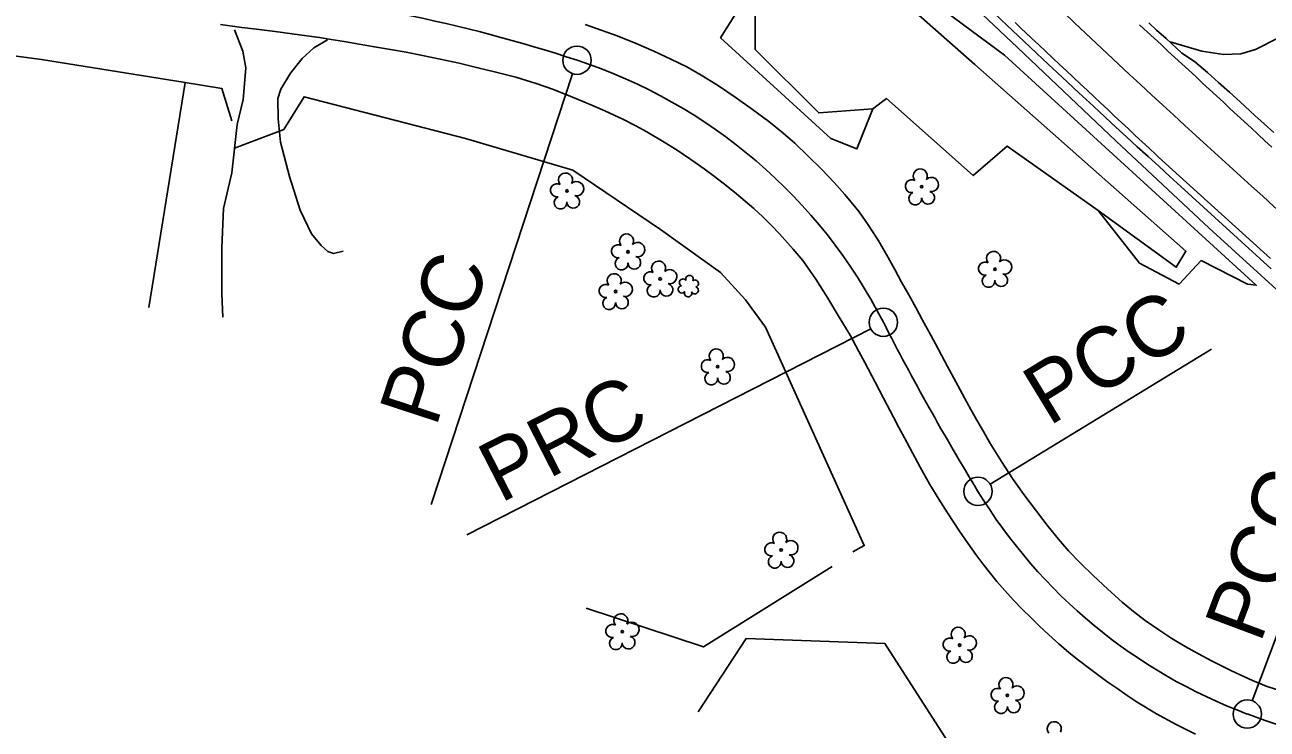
# Model space of a CAD drawing. Extents: x 474972 to 479313, y 498315 to 502691.
# Drawn here: x 476395.3 to 476724.1, y 500512.6 to 500699.1 of the extents above; entities that cross this region are included whole.
import ezdxf

# ---------------------------------------------------------------- set-up
doc = ezdxf.new("R2010")
doc.units = 0
for name, color, linetype in [('Exist Guardrail', 7, 'Continuous'), ('Exist Horizontal Alignment', 7, 'Continuous'), ('Exist Other Culture Fence Line', 7, 'Continuous'), ('Exist Other Culture Gate', 7, 'Continuous'), ('Exist Roads EOP', 7, 'Continuous'), ('Exist Roads EOT', 7, 'Continuous'), ('Exist Roads Soil', 7, 'Continuous'), ('Exist Vegetation Hedge Row', 7, 'Continuous'), ('Exist Vegetation Shrub CELL', 7, 'Continuous'), ('Exist Vegetation Tree CELL', 7, 'Continuous'), ('Exist Vegetation Woods Line', 7, 'Continuous')]:
    doc.layers.add(name, color=color, linetype=linetype)

msp = doc.modelspace()

# ---------------------------------------------------------------- linework, layer by layer
at = {"layer": 'Exist Guardrail'}
msp.add_lwpolyline([(476737.29, 500619.31), (476708.8, 500645.27), (476684.15, 500668.31), (476658.03, 500693.08), (476634.78, 500715.19), (476612.16, 500736.97), (476592.64, 500756.19), (476581.97, 500766.87)], dxfattribs=at)
at = {"layer": 'Exist Horizontal Alignment'}
for p, q in [((476540.3, 500686.15), (476502.88, 500572.1)), ((476619.19, 500618.65), (476512.3, 500564.04)), ((476650.77, 500577.53), (476709.4, 500613.27)), ((476720.16, 500520.15), (476742.19, 500578.94))]:
    msp.add_line(p, q, dxfattribs=at)
for centre in [(476541.46, 500689.72), (476622.53, 500620.35), (476647.57, 500575.58), (476718.85, 500516.64)]:
    msp.add_circle(centre, 3.75, dxfattribs=at)
for centre, radius, start, end in [((478884.49, 503049.53), 3226.8, 223.91157, 228.4381), ((476415.01, 500304.21), 405.72, 71.839, 85.4005), ((476497.81, 500556.65), 140.05, 27.0574, 71.839), ((477230, 500930.64), 682.12, 207.0574, 211.36729), ((476768.56, 500649.33), 141.7, 211.3673, 249.4634), ((476791.99, 500711.88), 208.48, 249.4634, 293.0343)]:
    msp.add_arc(centre, radius, start, end, dxfattribs=at)
at = {"layer": 'Exist Other Culture Fence Line'}
for points in [[(476437.8, 500683.85), (476399.76, 500689.93), (476351.74, 500696.3), (476294.41, 500702.48), (476246.36, 500709.31), (476234.18, 500710.79)], [(476428.15, 500624.27), (476437.8, 500683.85), (476447.45, 500682.25), (476450.13, 500673.64)], [(476463.87, 500671.4), (476469.23, 500680.07), (476511.97, 500668.99), (476540.37, 500660.6), (476563.59, 500644.88), (476579.46, 500633.51), (476586.06, 500626.29), (476591.34, 500619.04), (476617.5, 500561.23), (476614.47, 500559.55)], [(476609, 500555.67), (476574.9, 500534.42), (476543.85, 500544.63)]]:
    msp.add_lwpolyline(points, dxfattribs=at)
at = {"layer": 'Exist Other Culture Gate'}
msp.add_line((476463.87, 500671.4), (476450.85, 500666.47), dxfattribs=at)
at = {"layer": 'Exist Roads EOP'}
for points in [[(476725.18, 500634.51), (476722.2, 500637.21), (476719.22, 500639.91), (476716.24, 500642.63), (476713.25, 500645.35), (476710.25, 500648.08), (476707.26, 500650.82), (476704.25, 500653.56), (476701.27, 500656.29), (476698.33, 500658.98), (476695.43, 500661.63), (476692.58, 500664.24), (476689.74, 500666.83), (476686.91, 500669.43), (476684.09, 500672.03), (476681.26, 500674.64), (476678.12, 500677.55), (476674.31, 500681.08), (476669.86, 500685.23), (476664.75, 500689.98), (476659.67, 500694.76), (476655.28, 500698.9), (476651.57, 500702.41)], [(476705.15, 500511.33), (476700.03, 500513.84), (476694.83, 500516.65), (476689.74, 500519.77), (476687.03, 500521.58), (476684.3, 500523.44), (476681.71, 500525.27), (476679.19, 500527.09), (476676.72, 500528.94), (476674.22, 500530.88), (476671.64, 500532.97), (476668.99, 500535.21), (476666.3, 500537.63), (476663.75, 500540.02), (476661.53, 500542.17), (476659.37, 500544.34), (476657.01, 500546.8), (476654.68, 500549.33), (476652.59, 500551.75), (476648.86, 500556.39), (476646.98, 500558.9), (476644.89, 500561.84), (476642.7, 500565.02), (476639.47, 500569.91), (476637.23, 500573.49), (476634.88, 500577.44), (476632.31, 500581.99), (476629.52, 500587.11), (476628.1, 500589.76), (476626.66, 500592.46), (476625.22, 500595.2), (476622.55, 500600.27), (476620.35, 500604.46), (476617.63, 500609.66), (476616.08, 500612.64), (476613.72, 500616.9), (476610.85, 500621.66), (476607.81, 500626.73), (476604.67, 500631.76), (476601.22, 500636.67), (476598.68, 500639.66), (476595.02, 500643.75), (476592.88, 500646.05), (476590.61, 500648.3), (476588.26, 500650.46), (476583.68, 500654.35), (476580.95, 500656.52), (476577.82, 500658.95), (476575.1, 500660.99), (476572.77, 500662.67), (476568.21, 500665.73), (476564.99, 500667.8), (476559.92, 500670.79), (476556.83, 500672.42), (476553.73, 500673.99), (476548.84, 500676.33), (476546.16, 500677.5), (476543.27, 500678.71), (476540.27, 500679.96), (476535.26, 500681.95), (476530.64, 500683.59), (476525.26, 500685.23), (476519.98, 500686.58), (476515.25, 500687.73), (476510.26, 500688.9), (476505.21, 500690.04), (476500.54, 500691.01), (476496.28, 500691.81), (476492.07, 500692.56), (476487.87, 500693.29), (476483.78, 500694), (476479.87, 500694.66), (476476.39, 500695.23), (476473.29, 500695.72), (476469.92, 500696.21), (476466.12, 500696.73), (476461.62, 500697.31), (476456.63, 500697.92), (476452.79, 500698.42), (476447.08, 500699.21)], [(476543.63, 500699.17), (476546.59, 500698.15), (476552.05, 500696.15), (476557.11, 500694.15), (476561.75, 500692.11), (476566.27, 500690.03), (476570.5, 500687.93), (476574.34, 500685.8), (476578.68, 500683.09), (476583.34, 500679.92), (476587.93, 500676.67), (476592.25, 500673.48), (476595.95, 500670.53), (476599.13, 500667.76), (476602.5, 500664.52), (476606.23, 500660.82), (476609.5, 500657.38), (476612.37, 500654.16), (476616.16, 500649.55), (476618.56, 500646.17), (476621.18, 500642.08), (476623.79, 500637.48), (476625.54, 500634.29), (476627.38, 500630.97), (476629.26, 500627.62), (476631.1, 500624.27), (476632.91, 500620.94), (476634.65, 500617.72), (476636.33, 500614.64), (476637.94, 500611.65), (476639.51, 500608.68), (476642.23, 500603.61), (476644.08, 500600.19), (476645.69, 500597.26), (476647.27, 500594.46), (476649.01, 500591.41), (476650.74, 500588.43), (476653.76, 500583.47), (476656.72, 500578.98), (476659.75, 500574.75), (476663.06, 500570.35), (476666.18, 500566.3), (476668.86, 500562.91), (476671.5, 500559.86), (476674.65, 500556.62), (476678.07, 500553.29), (476681.94, 500549.73), (476685.77, 500546.27), (476688.72, 500543.77), (476691.83, 500541.43), (476695.42, 500538.93), (476698.9, 500536.65), (476702.44, 500534.53), (476705.91, 500532.55), (476709.41, 500530.72), (476714.47, 500528.15), (476718.3, 500526.36), (476720.25, 500525.49), (476723.88, 500524.03), (476729.31, 500522.29)], [(476692.78, 500699.62), (476694.85, 500697.72), (476697.34, 500695.44), (476701.54, 500691.63), (476704.85, 500689.41), (476708.28, 500686.48), (476711.23, 500683.85), (476714.11, 500681.25), (476716.93, 500678.69), (476720.85, 500675.13), (476723.29, 500672.9), (476725.87, 500670.56)]]:
    msp.add_lwpolyline(points, dxfattribs=at)
at = {"layer": 'Exist Roads EOT'}
for points in [[(476724.98, 500637.21), (476723.12, 500638.89), (476721.27, 500640.57), (476719.42, 500642.25), (476717.57, 500643.93), (476715.72, 500645.61), (476713.87, 500647.29), (476712.02, 500648.97), (476710.17, 500650.65), (476708.32, 500652.33), (476706.47, 500654.01), (476704.62, 500655.69), (476702.77, 500657.37), (476700.92, 500659.05), (476699.07, 500660.73), (476697.22, 500662.41), (476695.37, 500664.09), (476694.7, 500664.7), (476692.87, 500666.41), (476691.05, 500668.12), (476689.22, 500669.83), (476687.4, 500671.54), (476685.57, 500673.24), (476683.75, 500674.95), (476681.93, 500676.66), (476680.1, 500678.37), (476678.28, 500680.08), (476676.45, 500681.79), (476674.63, 500683.5), (476672.8, 500685.21), (476670.98, 500686.92), (476669.16, 500688.63), (476667.33, 500690.34), (476665.51, 500692.05), (476663.68, 500693.76), (476661.86, 500695.47), (476660.03, 500697.17), (476659.19, 500697.96), (476657.38, 500699.69)], [(476725.37, 500666.7), (476723.53, 500668.39), (476721.7, 500670.09), (476719.87, 500671.79), (476718.03, 500673.49), (476716.2, 500675.18), (476714.36, 500676.88), (476712.53, 500678.58), (476710.69, 500680.28), (476708.86, 500681.98), (476707.02, 500683.67), (476705.19, 500685.37), (476703.36, 500687.07), (476701.52, 500688.77), (476699.69, 500690.46), (476697.85, 500692.16), (476696.02, 500693.86), (476694.18, 500695.56), (476692.35, 500697.26), (476690.52, 500698.95), (476690.32, 500699.13)]]:
    msp.add_lwpolyline(points, dxfattribs=at)
at = {"layer": 'Exist Roads Soil'}
msp.add_line((476453.04, 500692.11), (476450.83, 500697.77), dxfattribs=at)
for points in [[(476698.43, 500694.57), (476706.83, 500692.14), (476712.54, 500691.21), (476717.15, 500691.43), (476721, 500692.58), (476727.29, 500695.72), (476733.62, 500700.65), (476743.74, 500710.34), (476757.73, 500725.73), (476770.36, 500737.78), (476783.01, 500748.93), (476797.48, 500762.55), (476812.27, 500777.94), (476819.37, 500785.2)], [(476475.39, 500695.14), (476471.79, 500692.99), (476468.73, 500690.18), (476465.66, 500686.32), (476463.1, 500682.07), (476462.29, 500679.56), (476462.38, 500674.16), (476462.98, 500668.02), (476465.33, 500658.95), (476468.23, 500650), (476471.2, 500643.75), (476473.75, 500640.66), (476475.54, 500639.08), (476477.06, 500638.52), (476479.6, 500639.18)], [(476447.74, 500621.69), (476447.45, 500627.87), (476447.5, 500640.05), (476447.93, 500650.44), (476450.14, 500659.93), (476451.52, 500672.7), (476453.09, 500679.29), (476453.86, 500687.71), (476453.04, 500692.11)]]:
    msp.add_lwpolyline(points, dxfattribs=at)
at = {"layer": 'Exist Vegetation Hedge Row'}
for points in [[(476586.98, 500753.69), (476594.5, 500750.7), (476628.01, 500716.75), (476632.55, 500707.49), (476654.57, 500691.08), (476721.24, 500630.13), (476718.92, 500630.47), (476706.65, 500636.66), (476700.86, 500630.44), (476690.28, 500636), (476679.38, 500649.98)], [(476619.72, 500676.82), (476615.54, 500666.22), (476608.61, 500669.04), (476579.48, 500695.65), (476587.09, 500707.88), (476600.68, 500710.32)]]:
    msp.add_lwpolyline(points, dxfattribs=at)
at = {"layer": 'Exist Vegetation Shrub CELL'}
msp.add_line((476571, 500629.74), (476571, 500629.74), dxfattribs=at)
for centre, radius, start, end in [((476571.23, 500631.78), 0.99, 334.8391, 200.4717), ((476569.2, 500629.04), 0.955, 95.1099, 327.9534), ((476569.52, 500630.87), 0.968, 35.8908, 245.4216), ((476572.64, 500628.81), 0.937, 204.9913, 73.4601), ((476572.68, 500630.61), 0.929, 284.4567, 126.0861), ((476570.87, 500628.06), 0.984, 151.2797, 21.387)]:
    msp.add_arc(centre, radius, start, end, dxfattribs=at)
at = {"layer": 'Exist Vegetation Tree CELL'}
for p, q in [((476538.79, 500655.13), (476538.79, 500655.13)), ((476632.69, 500656.22), (476632.69, 500656.22)), ((476554.94, 500639), (476554.94, 500639)), ((476652.06, 500634.39), (476652.06, 500634.39)), ((476563.46, 500631.83), (476563.46, 500631.83)), ((476551.67, 500628.49), (476551.67, 500628.49)), ((476578.69, 500608.58), (476578.69, 500608.58)), ((476595.5, 500560.06), (476595.5, 500560.06)), ((476553.44, 500538.46), (476553.44, 500538.46)), ((476642.72, 500534.87), (476642.72, 500534.87)), ((476655.37, 500521.58), (476655.37, 500521.58))]:
    msp.add_line(p, q, dxfattribs=at)
for centre in [(476538.79, 500655.13), (476632.69, 500656.22), (476554.94, 500639), (476563.46, 500631.83), (476652.06, 500634.39), (476551.67, 500628.49), (476578.69, 500608.58), (476595.5, 500560.06), (476553.44, 500538.46), (476642.72, 500534.87), (476655.37, 500521.58)]:
    msp.add_circle(centre, 0.326, dxfattribs=at)
for centre, radius, start, end in [((476538.41, 500658.01), 1.86, 330.1651, 219.7134), ((476632.31, 500659.09), 1.86, 330.1651, 219.7134), ((476635.24, 500656.81), 1.9, 257.1011, 134.1999), ((476536.19, 500655.29), 1.73, 62.6636, 279.3457), ((476541.34, 500655.72), 1.9, 257.1011, 134.1999), ((476630.09, 500656.37), 1.73, 62.6636, 279.3457), ((476537.09, 500652.01), 1.69, 111.5671, 6.231), ((476540.46, 500652.23), 1.7, 181.2822, 74.56), ((476630.99, 500653.1), 1.69, 111.5671, 6.231), ((476634.37, 500653.32), 1.7, 181.2822, 74.56), ((476554.56, 500641.87), 1.86, 330.1651, 219.7134), ((476552.34, 500639.15), 1.73, 62.6636, 279.3457), ((476557.49, 500639.59), 1.9, 257.1011, 134.1999), ((476651.68, 500637.27), 1.86, 330.1651, 219.7134), ((476553.24, 500635.88), 1.69, 111.5671, 6.231), ((476556.62, 500636.1), 1.7, 181.2822, 74.56), ((476563.07, 500634.7), 1.86, 330.1651, 219.7134), ((476649.46, 500634.55), 1.73, 62.6636, 279.3457), ((476654.61, 500634.98), 1.9, 257.1011, 134.1999), ((476551.29, 500631.36), 1.86, 330.1651, 219.7134), ((476560.85, 500631.98), 1.73, 62.6636, 279.3457), ((476566.01, 500632.42), 1.9, 257.1011, 134.1999), ((476650.36, 500631.27), 1.69, 111.5671, 6.231), ((476653.73, 500631.49), 1.7, 181.2822, 74.56), ((476549.07, 500628.64), 1.73, 62.6636, 279.3457), ((476554.22, 500629.08), 1.9, 257.1011, 134.1999), ((476561.75, 500628.71), 1.69, 111.5671, 6.231), ((476565.13, 500628.93), 1.7, 181.2822, 74.56), ((476549.97, 500625.37), 1.69, 111.5671, 6.231), ((476553.35, 500625.59), 1.7, 181.2822, 74.56), ((476578.31, 500611.45), 1.86, 330.1651, 219.7134), ((476576.08, 500608.73), 1.73, 62.6636, 279.3457), ((476581.24, 500609.17), 1.9, 257.1011, 134.1999), ((476576.99, 500605.46), 1.69, 111.5671, 6.231), ((476580.36, 500605.68), 1.7, 181.2822, 74.56), ((476595.11, 500562.93), 1.86, 330.1651, 219.7134), ((476592.89, 500560.21), 1.73, 62.6636, 279.3457), ((476598.05, 500560.65), 1.9, 257.1011, 134.1999), ((476593.79, 500556.94), 1.69, 111.5671, 6.231), ((476597.17, 500557.16), 1.7, 181.2822, 74.56), ((476550.83, 500538.61), 1.73, 62.6636, 279.3457), ((476553.05, 500541.33), 1.86, 330.1651, 219.7134), ((476555.99, 500539.05), 1.9, 257.1011, 134.1999), ((476551.73, 500535.34), 1.69, 111.5671, 6.231), ((476555.11, 500535.56), 1.7, 181.2822, 74.56), ((476642.34, 500537.74), 1.86, 330.1651, 219.7134), ((476645.27, 500535.46), 1.9, 257.1011, 134.1999), ((476640.11, 500535.02), 1.73, 62.6636, 279.3457), ((476644.39, 500531.97), 1.7, 181.2822, 74.56), ((476641.02, 500531.75), 1.69, 111.5671, 6.231), ((476654.99, 500524.45), 1.86, 330.1651, 219.7134), ((476657.92, 500522.17), 1.9, 257.1011, 134.1999), ((476652.77, 500521.73), 1.73, 62.6636, 279.3457), ((476653.67, 500518.46), 1.69, 111.5671, 6.231), ((476657.05, 500518.68), 1.7, 181.2822, 74.56), ((476667.78, 500512.76), 1.86, 330.1651, 219.7134)]:
    msp.add_arc(centre, radius, start, end, dxfattribs=at)
at = {"layer": 'Exist Vegetation Woods Line'}
for points in [[(476572.06, 500768.46), (476586.98, 500753.69), (476607.9, 500728.42), (476630.41, 500702.99), (476646.77, 500688.59), (476702.61, 500639.16), (476700.03, 500634.92), (476679.38, 500649.98), (476679.38, 500649.98), (476655.29, 500666.98), (476646.31, 500659.19), (476623.34, 500679.55), (476619.72, 500676.82), (476619.72, 500676.82), (476605.42, 500675.79), (476588.57, 500692.57), (476588.57, 500705.64), (476600.68, 500710.32)], [(476573.5, 500517.25), (476586.22, 500536.61), (476622.96, 500535.28), (476643.4, 500503.47), (476621.57, 500502.91), (476621.78, 500488.55), (476648.96, 500473.98), (476647.9, 500451.75), (476647.15, 500449.22)]]:
    msp.add_lwpolyline(points, dxfattribs=at)

# ---------------------------------------------------------------- texts
at = {"layer": 'Exist Horizontal Alignment'}
for s, rotation, p in [('PCC', 71.839, (476504.11, 500592.3)), ('PCC', 31.3673, (476666.33, 500592.7)), ('PRC', 27.0574, (476521.16, 500572.34)), ('PCC', 69.4634, (476722.25, 500535.1))]:
    msp.add_text(s, height=16, rotation=rotation, dxfattribs=at).set_placement(p)

doc.saveas('drawing.dxf')
